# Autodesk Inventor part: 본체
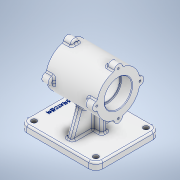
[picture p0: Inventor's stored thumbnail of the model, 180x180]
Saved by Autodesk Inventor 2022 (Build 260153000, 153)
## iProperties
Created: 2023-05
Part Number: 본체
Material: 알루미늄 6061
Document SubType Name: Modeling
Designer: Admin
Density: 2.7 g/cm^3
Appearance: 알루미늄 - 평지
Mass: 1215.39 g
Surface Area: 796.917 cm^2
Volume: 450.145 cm^3
Author: Admin
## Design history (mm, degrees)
sketch "스케치1"
  geometry: L1 (-78.381, 0)-(72.862, 0) reference; L2 (0, -7.4)-(0, 44.4) reference; L3 (-56.775, 0)-(51.256, 0); L4 (-43.5, 0)-(-43.5, 37); L5 (-43.5, 37)-(43.5, 37); L6 (43.5, 37)-(43.5, 0); 1 further point
  constraints: 8 end point, 4 point on line, 3 perpendicular, 1 other
  dimensions: "d0" = 74 diameter of L5 L3; "d1" = 87 distance of L4.end L5.end
revolve "회전1" sketch "스케치1" stored, may be unused: angle "d2" = 90 deg
node "작업 평면1"
sketch "스케치3"
  geometry: L1 (70, 55)-(-60, 55); L2 (-60, 55)-(-60, -55); L3 (-60, -55)-(70, -55); L4 (70, -55)-(70, 55); L5 (0, -77)-(0, 77) reference; L6 (96, 0)-(-86, 0) reference; 1 further point
  constraints: 8 end point, 2 parallel, 1 horizontal, 1 perpendicular
  dimensions: "d11" = 130 distance of L1.start L1.end; "d12" = 110 distance of L3.end L1.start; "d13" = 70 distance between parallel lines of L5 L4; "d14" = 55 distance between parallel lines of L6 L1
extrude "돌출2" join sketch "스케치3" distance "d15" = 12; taper "d16" = 0 deg
sketch "스케치4"
  geometry: L1 (-20, -27.453)-(-20, -74.651); L2 (-20, -74.651)-(20, -74.651); L3 (20, -74.651)-(20, -27.453); L4 (20, -27.453)-(-20, -27.453); L5 (0, -89.581)-(0, 14.93) reference; L6 (-28, 0)-(28, 0) reference; 1 further point
  constraints: 8 end point, 1 horizontal, 1 parallel, 1 perpendicular, 1 vertical, 1 other
  dimensions: "d17" = 40 distance of L3.end L1.start; "d18" = 47.19748 distance between parallel lines of L2 L4; "d19" = 27.45319 distance between parallel lines of L6 L4
extrude "돌출3" join sketch "스케치4" stored distance "d20" = 10; taper "d21" = 0 deg
sketch "스케치5"
  geometry: L1 (-24.719, -24.519)-(-70, -41); L2 (-70, -41)-(-70, 41); L3 (-70, 41)-(-24.719, 24.519); L4 (-24.719, 24.519)-(-24.719, -24.519); L5 (-70, 55)-(-70, -55) reference; L6 (-84, 0)-(14, 0) reference; L7 (0, -77)-(0, 77) reference; L8 (-82, 77)-(-82, -77) reference; 1 further point
  constraints: 8 end point, 1 parallel, 1 vertical
  dimensions: "d22" = 110 deg angle of L5 L3; "d23" = 110 deg angle of L5 L1; "d24" = 82 distance of L1.end L2.end; "d25" = 41 distance from line of L6 L2.end; "d26" = 45.28124 distance between parallel lines of L5 L4; "d27" = 12 distance between parallel lines of L8 L2
extrude "돌출4" join sketch "스케치5" stored distance "d28" = 10; taper "d29" = 0 deg
sketch "스케치6"
  geometry: L1 (-81.048, 0)-(86.657, 0); L2 (-114.589, 0)-(120.198, 0) reference; L3 (0, -105.8)-(0, 60.8) reference; L4 (-43.5, -37)-(-43.5, 37) reference; L5 (-43.5, 23.5)-(-25.5, 23.5); L6 (-24.5, 22.5)-(-24.5, 21); L7 (-24.5, 21)-(24.5, 21); L8 (24.5, 21)-(24.5, 22.5); L9 (25.5, 23.5)-(43.5, 23.5); L10 (43.5, -37)-(43.5, 37) reference; A1 r 1 centre (-25.5, 22.5) between (-24.5, 22.5) and (-25.5, 23.5); A2 r 1 centre (25.5, 22.5) between (25.5, 23.5) and (24.5, 22.5); 4 further points
  constraints: 12 end point, 6 point on line, 4 point on circle, 4 tangent, 3 horizontal, 3 perpendicular, 2 centre point, 1 equal radius, 1 other
  dimensions: "d32" = 47 diameter of L9 L1; "d33" = 42 diameter of L7 L1; "d34" = 49 distance between parallel lines of L8 L6; "d35" = 1 radius of A1
revolve "회전2" sketch "스케치6" stored, may be unused: angle "d36" = 90 deg
chamfer "모따기1" distance "d37" = 1; stored, may be unused: second distance "d38" = 2, angle "d39" = 45 deg
sketch "스케치8"
  geometry: L1 (0, -105.8)-(0, 60.8) reference; L2 (-77, 0)-(77, 0) reference; C1 r 37 at (0, 0); C2 r 7 at (0, 37); C3 r 7 at (-37, 0); C4 r 7 at (0, -37); C5 r 7 at (37, 0); 1 further point
  constraints: 5 centre point, 1 coincident, 1 point on line, 9 other
  dimensions: "d40" = 74 diameter of C1; "d41" = 14 diameter of C2; "d42" = 37 distance of point (0, 0) C2.centre; "d45" = 360 deg dimension on point (0, 0) C2.centre (derived)
extrude "돌출5" join sketch "스케치8" distance "d47" = 14; taper "d48" = 0 deg
sketch "스케치9"
  geometry: A1 r 7 centre (-37, 37) between (-30.031, 36.338) and (-43.969, 36.338) reference; A2 r 7 centre (0, 0) between (-0.662, -6.969) and (-0.662, 6.969) reference; A3 r 7 centre (-37, -37) between (-43.969, -36.338) and (-30.031, -36.338) reference; A4 r 7 centre (-74, 0) between (-73.338, 6.969) and (-73.338, -6.969) reference; 5 further points
  constraints: 4 coincident
hole "구멍1" sketch "스케치9" at (-37, 37), (0, 0), (-37, -37), (-74, 0) diameter "d49" = 3.242; stored, may be unused: countersink angle "d53" = 90 deg, drill point angle "d55" = 118 deg; dims "d50" = 8, "d51" = 4, "d52" = 2, "d54" = 10
fillet "모깎기1" dims "d56" = 3
fillet "모깎기2" dims "d57" = 3
fillet "모깎기3" dims "d58" = 12
sketch "스케치10"
  geometry: A1 r 12 centre (-58, 43) between (-58, 55) and (-70, 43) reference; A2 r 12 centre (-58, -43) between (-70, -43) and (-58, -55) reference; A3 r 12 centre (48, -43) between (48, -55) and (60, -43) reference; A4 r 12 centre (48, 43) between (60, 43) and (48, 55) reference; 5 further points
  constraints: 4 coincident
hole "구멍2" sketch "스케치10" at (-58, 43), (-58, -43), (48, -43), (48, 43) diameter "d59" = 9; stored, may be unused: countersink angle "d63" = 90 deg, drill point angle "d65" = 0 deg; dims "d60" = 8, "d61" = 4, "d62" = 2, "d64" = 12
fillet "모깎기4" dims "d66" = 3
sketch "스케치11"
  geometry: L1 (-96, 0)-(86, 0) reference; L2 (0, 77)-(0, -77) reference; 2 further points
  constraints: 1 point on line, 1 other
  dimensions: "d67" = 58 distance from line of L2 point (-58, 0)
feature "엠보싱1" sketch "스케치11" dims "d0" = 74, "d1" = 87, "d17" = 40, "d18" = 47.19748, "d19" = 27.45319, "d68" = 0.5, "d69" = 0
node "솔리드1"
mirror "미러2"
mirror "미러3"
feature "A9D066F2-1C7D-4E18-AEED-F7BC21143FA4" dims "d59" = 9, "d60" = 8, "d61" = 4, "d62" = 2, "d63" = 90 deg, "d64" = 12, "d65" = 0
other parameters: "d10" = -82
